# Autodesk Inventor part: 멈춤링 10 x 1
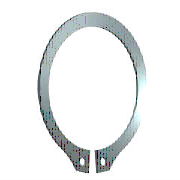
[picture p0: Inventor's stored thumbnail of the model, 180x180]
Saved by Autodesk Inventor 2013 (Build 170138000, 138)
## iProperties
IsCustomPart: 0
Company: 한국ATC센터
Created: 2009-02
Part Number: 멈춤링 10 x 1
Material: Steel, Mild
Description: 리테이닝 링(C형)
Document SubType Name: Modeling
Standard: KS B 1336
Designer: KYOUNG IL JANG
Standards Organization: KS
Language: ko-KR
Size Designation: 10 x 1
Categories: <MemberInstance><Categories><Category DisplayName="샤프트 부품" InternalName="7f7aeb1f-a693-4053-b835-cee3144e0d98" Mnemonic="SHFT"><Category DisplayName="써클립" Inter
Density: 7.86 g/cm^3
Mass: 0.423084 g
Surface Area: 1.9243 cm^2
Volume: 0.0538275 cm^3
Author: KYOUNG IL JANG
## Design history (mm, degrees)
sketch "스케치1"
  geometry: L1 (-6, 0)-(6, 0) reference; L2 (0, 20.189)-(0, -80.536) reference; L3 (-48.09, 0)-(48.09, 0) reference; L4 (-0.3, -9.791)-(-0.3, -12.791); L5 (-0.3, -6.54)-(-0.3, -13.29); L6 (-2.795, 1.6)-(3.672, 1.6); L7 (0.3, -6.54)-(0.3, -13.29); L8 (0.3, -9.791)-(0.3, -12.791); C1 r 0.6 at (-1.2, -11.486); C2 r 0.6 at (1.2, -11.486); A1 r 4.8 centre (0, -5) between (0.3, -9.791) and (-0.3, -9.791); A2 r 6.2 centre (0, -4.6) between (2.988, -10.033) and (-2.988, -10.033); A3 r 7.796 centre (0, -5) between (-1.418, -12.666) and (-0.3, -12.791); A4 r 1.2 centre (-1.2, -11.486) between (-2.383, -11.285) and (-1.418, -12.666); A5 r 1.2 centre (-3.566, -11.084) between (-2.383, -11.285) and (-2.988, -10.033); A6 r 1.2 centre (3.566, -11.084) between (2.988, -10.033) and (2.383, -11.285); A7 r 1.2 centre (1.2, -11.486) between (1.418, -12.666) and (2.383, -11.285); A8 r 7.796 centre (0, -5) between (0.3, -12.791) and (1.418, -12.666)
  constraints: 16 point on circle, 12 end point, 10 centre point, 9 symmetric about line, 5 point on line, 4 tangent, 3 coincident, 2 horizontal, 1 perpendicular, 1 vertical, 5 other
  dimensions: "d0" = 9.6 diameter of A1 (= ND); "d1" = 3 distance of L4.end L4.start (= SRB2); "d6" = 0.3 distance between parallel lines of L2 L5 (= 0.25 x SD5); "d7" = 1.6 distance between parallel lines of L6 L3 (= SRB1); "d8" = 0.4 distance of A1.centre A2.centre (= 0.25 x SRB1); "d9" = 1.2 radius of A4 (= SD5); "d10" = 1.2 radius of A5 (= SD5); "d11" = 0.9 distance from line of L4 A4.centre (= 0.75 x SD5); "d12" = 1.2 diameter of C1 (= SD5); "d13" = 1.2 diameter of C2 (= SD5); "d14" = 5 distance from line of A1.centre L1 (= 0.5 x WD)
extrude "본체" new body sketch "스케치1" distance "d2" = 1 (= SD); taper "d3" = 0 deg
workaxis "Work Axis1"
workplane "Work Plane1"
body "Solid1"
other parameters: "SD" = 1 [user parameter; used in 1 equation term], "SRB1" = 1.6 [user parameter; used in 2 equation terms], "ND" = 9.6 [user parameter; used in 1 equation term], "SRB2" = 3 [user parameter; used in 1 equation term], "SD5" = 1.2 [user parameter; used in 6 equation terms], "d15" = 0, "d16" = 0, "d17" = 0, "d41" = 0, "d42" = 0, "SD3" = 9.3 [user parameter], "WDMAX" = 11 [user parameter]
